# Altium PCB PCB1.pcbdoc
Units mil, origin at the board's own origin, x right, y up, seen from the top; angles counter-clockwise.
Board outline 1010 x 987.15 mil, 2 copper layers (Top Layer, Bottom Layer); 12 components, 8 nets, 48 pads, 12 vias.
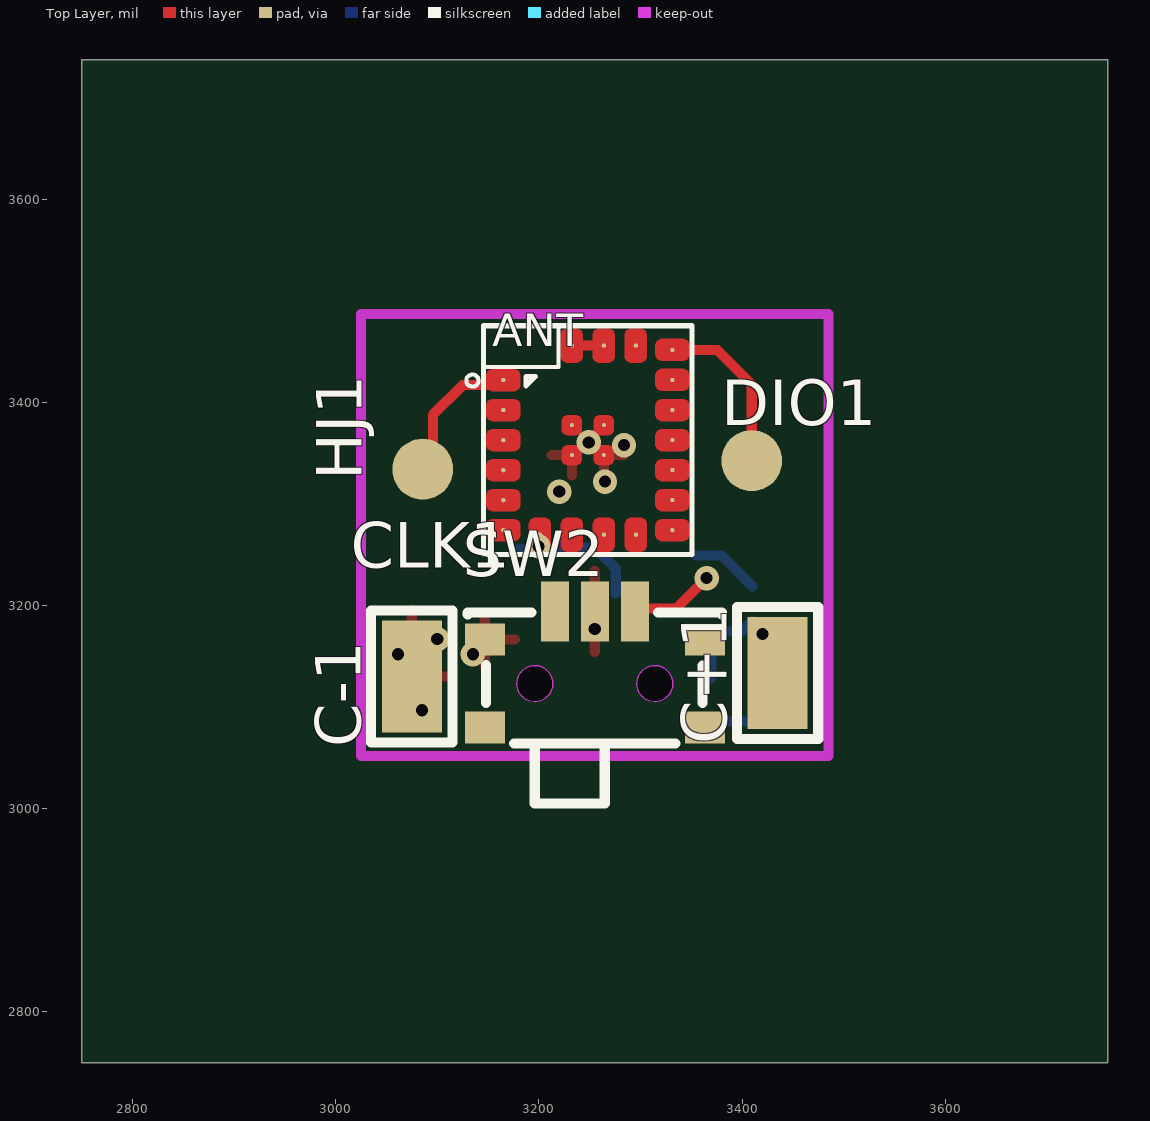
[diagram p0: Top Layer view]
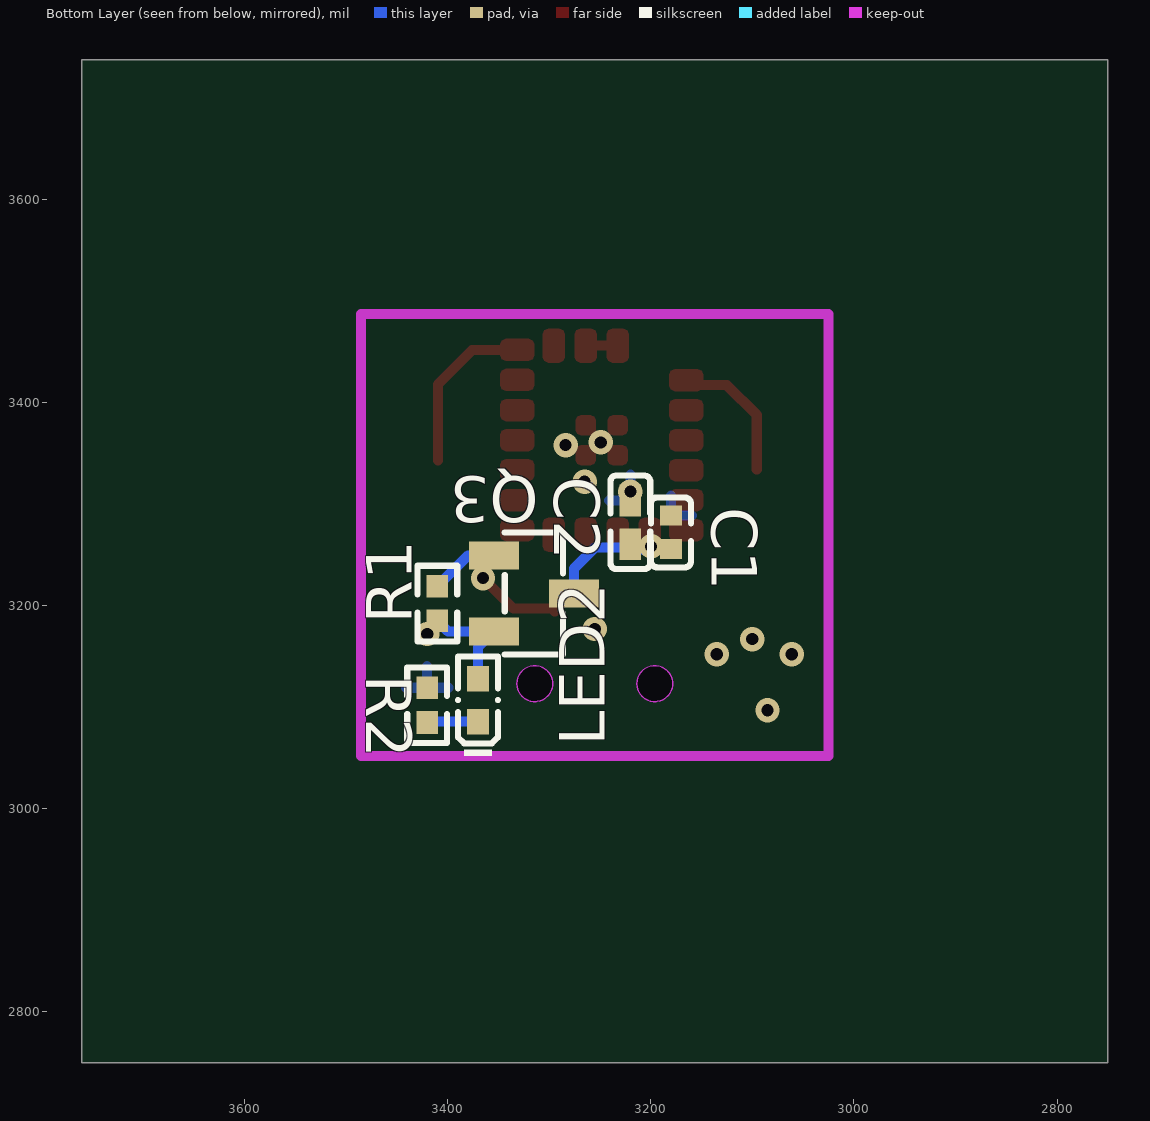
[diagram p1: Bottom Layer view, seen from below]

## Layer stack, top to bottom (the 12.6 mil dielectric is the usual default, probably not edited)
Top Layer: signal copper (thickness not stored)
Dielectric: dielectric 12.6, FR-4, Dk 4.8
Bottom Layer: signal copper (thickness not stored)

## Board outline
3760,2750 2750,2750 2750,3737.15 3760,3737.15

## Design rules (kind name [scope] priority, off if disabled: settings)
BoardOutlineClearance copperThickness1oz [All] p0: genericclearance=10 ignorepadtopadclearanceinfootprint=FALSE except(0: Arc-SplitContinuation Track-SplitContinuation SMDPad-SplitContinuation THPad-SplitContinuation Via-SplitContinuation Fill-SplitContinuation Poly-SplitContinuation Region-SplitContinuation Text-SplitContinuation; 6: Track-CutoutEdge SMDPad-CutoutEdge THPad-CutoutEdge Via-CutoutEdge Region-CutoutEdge; 11.8: Track-OutlineEdge SMDPad-OutlineEdge THPad-OutlineEdge Via-OutlineEdge Fill-OutlineEdge Region-OutlineEdge Poly-OutlineEdge Text-OutlineEdge Fill-CutoutEdge)
BoardOutlineClearance copperThickness2oz [All] p0: genericclearance=10 ignorepadtopadclearanceinfootprint=FALSE except(0: Arc-SplitContinuation Track-SplitContinuation SMDPad-SplitContinuation THPad-SplitContinuation Via-SplitContinuation Fill-SplitContinuation Poly-SplitContinuation Region-SplitContinuation Text-SplitContinuation; 6: Track-CutoutEdge SMDPad-CutoutEdge THPad-CutoutEdge Via-CutoutEdge Region-CutoutEdge; 11.8: Track-OutlineEdge SMDPad-OutlineEdge THPad-OutlineEdge Via-OutlineEdge Fill-OutlineEdge Region-OutlineEdge Poly-OutlineEdge Text-OutlineEdge Fill-CutoutEdge)
Clearance copperThickness1oz [(InNet('+3.3V') OR InNet('GND') OR InNet('$1N942') OR InNet('$1N941') OR InNet('$1N931') OR InNet('$1N605') OR InNet('$1N1928') OR InNet('$1N1997'))] p1: gap=7 ignorepadtopadclearanceinfootprint=FALSE except(4: Track-Track; 6: Track-SMDPad SMDPad-SMDPad Track-THPad SMDPad-THPad THPad-THPad Track-Via SMDPad-Via THPad-Via Via-Via SMDPad-Fill THPad-Fill Via-Fill Fill-Fill Track-Region SMDPad-Region THPad-Region Via-Region Region-Region Track-Poly SMDPad-Poly THPad-Poly Via-Poly Fill-Poly Region-Poly Poly-Poly Track-Text SMDPad-Text THPad-Text Via-Text Fill-Text Region-Text Poly-Text Text-Text; 6.9: Track-Hole SMDPad-Hole THPad-Hole Via-Hole Fill-Hole Region-Hole Poly-Hole Text-Hole Sheet-Hole; 11.8: Track-Fill Fill-Region Track-Sheet SMDPad-Sheet THPad-Sheet Via-Sheet Fill-Sheet Region-Sheet Poly-Sheet Text-Sheet)
Clearance copperThickness2oz [All] p1: gap=7 ignorepadtopadclearanceinfootprint=FALSE except(6: Track-SMDPad SMDPad-SMDPad Track-THPad SMDPad-THPad THPad-THPad Track-Via SMDPad-Via THPad-Via Via-Via SMDPad-Fill THPad-Fill Via-Fill Fill-Fill Track-Region SMDPad-Region THPad-Region Via-Region Region-Region Track-Poly SMDPad-Poly THPad-Poly Via-Poly Fill-Poly Region-Poly Poly-Poly Track-Text SMDPad-Text THPad-Text Via-Text Fill-Text Region-Text Poly-Text Text-Text; 6.9: Track-Hole SMDPad-Hole THPad-Hole Via-Hole Fill-Hole Region-Hole Poly-Hole Text-Hole Sheet-Hole; 8: Track-Track; 11.8: Track-Fill Fill-Region Track-Sheet SMDPad-Sheet THPad-Sheet Via-Sheet Fill-Sheet Region-Sheet Poly-Sheet Text-Sheet)
DiffPairsRouting differentialPair [All] p1: maxuncoupledlength=10 minlimit=6 maxlimit=6 mostfreqgap=6 toplayer_minwidth=5 toplayer_prefwidth=10 toplayer_maxwidth=100 bottomlayer_minwidth=5 bottomlayer_prefwidth=10 bottomlayer_maxwidth=100
PasteMaskExpansion pasteMaskExpansion [All] p1: expansion=0
PlaneConnect innerPlane [All] p1: planeconnectstyle=Relief reliefexpansion=20 reliefentries=4 reliefconductorwidth=10 reliefairgap=10
PolygonConnect copperRegion [All] p1: connectstyle=Relief reliefentries=4 reliefconductorwidth=10 polygonreliefangle="90 Angle" airgapwidth=10
RoutingVias viaSize [All] p1: viastyle="Through Hole" holewidth=12.0078 minholewidth=11.811 maxholewidth=248.0314 width=24.0158 minwidth=19.685 maxwidth=393.7008
SolderMaskExpansion solderMaskExpansion [All] p1: useseparateexpansions=TRUE expansion=2 expansionbottom=2
Width copperThickness1oz [All] p1: maxlimit=100 minlimit=5 preferedwidth=10
Width copperThickness2oz [All] p1: maxlimit=100 minlimit=8 preferedwidth=10

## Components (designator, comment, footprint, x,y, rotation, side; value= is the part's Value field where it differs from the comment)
C1 "CL05A105KA5NQNC" C0402#1 3180,3271.89 r270 bottom
C2 "10u" C0402#2 3220,3281.89 r270 bottom
C+1 "RH-5015" SMD_RH-5015 3435,3133.63 r90 top
C-1 "RH-5015" SMD_RH-5015 3074.86,3130.2 r90 top
CLK1 "TESTPOINT_D1.5mm" TESTPOINT_D1.5MM 3085.66,3334.12 r0 top
DIO1 "TESTPOINT_D1.5mm" TESTPOINT_D1.5MM 3409.49,3342.52 r0 top
HJ1 "HJ-180IMH" HJ-180IMH(LGA21) 3165,3421.89 r90 top
LED2 "XL-1005UGC_C2856703" LED0402-RD_GREEN 3370,3106.89 r90 bottom
Q3 "IRLML6401TRPBF" SOT-23-3_L2.9-W1.3-P1.90-LS2.4-BR 3315,3211.89 r0 bottom
R1 "10kΩ" R0402 3410,3201.89 r90 bottom
R2 "4.7K" R0402 3420,3101.89 r270 bottom
SW2 "MINI MSK12CO2" SW-SMD_MSK12CO2 3255,3136.89 r0 top

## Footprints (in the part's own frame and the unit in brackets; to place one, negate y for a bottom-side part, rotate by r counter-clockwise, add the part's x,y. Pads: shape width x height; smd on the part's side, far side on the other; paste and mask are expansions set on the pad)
C0402#1 [mm]
  rect 0.5x0.54 smd: 1(-0.42,0) 2(0.42,0)
  silkscreen extent -0.87,-0.5 0.87,0.5
C0402#2 [mm]
  rect 0.79x0.54 smd: 1(-0.545,0) 2(0.545,0)
  silkscreen extent -1.17,-0.5 1.17,0.5
HJ-180IMH(LGA21) [mm]
  round 0.11 smd: 1(0,0) 2(-0.75,0) 3(-1.501,0) 4(-2.251,0) 5(-3.002,0) 6(-3.752,0) 7(-3.865,-0.914) 8(-3.865,-1.714) 9(-3.865,-2.515) 10(-3.865,-3.315) 11(-3.751,-4.227) 12(-3.001,-4.227) 13(-2.25,-4.227) 14(-1.5,-4.227) 15(-0.75,-4.227) 16(0.001,-4.227) 17(0.751,-4.227) 18(0.862,-3.313) 19(0.862,-2.513) 20(0.862,-1.713)
  round 0.1 smd: 21(-1.876,-1.713) 21(-1.875,-2.513) 21(-1.126,-2.513) 21(-1.126,-1.713)
  Top Layer region: -0.137,0.425 0.137,0.425 0.235,0.385 0.275,0.288 0.275,-0.288 0.235,-0.385 0.137,-0.425 -0.137,-0.425 -0.235,-0.385 -0.275,-0.288 -0.275,0.288 -0.235,0.385
  Top Layer region: -0.888,0.425 -0.613,0.425 -0.516,0.385 -0.475,0.288 -0.475,-0.288 -0.516,-0.385 -0.613,-0.425 -0.888,-0.425 -0.985,-0.385 -1.025,-0.288 -1.025,0.288 -0.985,0.385
  Top Layer region: -1.638,0.425 -1.363,0.425 -1.266,0.385 -1.226,0.288 -1.226,-0.288 -1.266,-0.385 -1.363,-0.425 -1.638,-0.425 -1.736,-0.385 -1.776,-0.288 -1.776,0.288 -1.736,0.385
  Top Layer region: -2.389,0.425 -2.114,0.425 -2.016,0.385 -1.976,0.288 -1.976,-0.288 -2.016,-0.385 -2.114,-0.425 -2.389,-0.425 -2.486,-0.385 -2.526,-0.288 -2.526,0.288 -2.486,0.385
  Top Layer region: -3.139,0.425 -2.864,0.425 -2.767,0.385 -2.727,0.288 -2.727,-0.288 -2.767,-0.385 -2.864,-0.425 -3.139,-0.425 -3.236,-0.385 -3.277,-0.288 -3.277,0.288 -3.236,0.385
  Top Layer region: -3.89,0.425 -3.614,0.425 -3.517,0.385 -3.477,0.288 -3.477,-0.288 -3.517,-0.385 -3.614,-0.425 -3.89,-0.425 -3.987,-0.385 -4.027,-0.288 -4.027,0.288 -3.987,0.385
  Top Layer region: -4.29,-1.052 -4.29,-0.777 -4.25,-0.679 -4.152,-0.639 -4.152,-0.639 -3.577,-0.639 -3.577,-0.639 -3.48,-0.679 -3.44,-0.777 -3.44,-1.052 -3.48,-1.149 -3.577,-1.189 -4.152,-1.189 -4.25,-1.149
  Top Layer region: -4.29,-1.852 -4.29,-1.577 -4.25,-1.48 -4.152,-1.439 -3.577,-1.439 -3.48,-1.48 -3.44,-1.577 -3.44,-1.852 -3.48,-1.949 -3.577,-1.989 -4.152,-1.989 -4.25,-1.949
  Top Layer region: -4.29,-2.652 -4.29,-2.377 -4.25,-2.28 -4.152,-2.24 -3.577,-2.24 -3.48,-2.28 -3.44,-2.377 -3.44,-2.652 -3.48,-2.749 -3.577,-2.79 -4.152,-2.79 -4.25,-2.749
  Top Layer region: -4.29,-3.452 -4.29,-3.177 -4.25,-3.08 -4.152,-3.04 -3.577,-3.04 -3.48,-3.08 -3.44,-3.177 -3.44,-3.452 -3.48,-3.55 -3.577,-3.59 -4.152,-3.59 -4.25,-3.55
  Top Layer region: -3.614,-4.652 -3.888,-4.652 -3.986,-4.612 -4.026,-4.514 -4.026,-3.939 -3.986,-3.842 -3.888,-3.802 -3.614,-3.802 -3.516,-3.842 -3.476,-3.939 -3.476,-4.514 -3.516,-4.612
  Top Layer region: -2.863,-4.652 -3.138,-4.652 -3.235,-4.612 -3.276,-4.514 -3.276,-3.939 -3.235,-3.842 -3.138,-3.802 -2.863,-3.802 -2.766,-3.842 -2.726,-3.939 -2.726,-4.514 -2.766,-4.612
  Top Layer region: -2.113,-4.652 -2.388,-4.652 -2.485,-4.612 -2.525,-4.514 -2.525,-3.939 -2.485,-3.842 -2.388,-3.802 -2.113,-3.802 -2.016,-3.842 -1.975,-3.939 -1.975,-4.514 -2.016,-4.612
  Top Layer region: -1.363,-4.652 -1.638,-4.652 -1.735,-4.612 -1.775,-4.514 -1.775,-3.939 -1.735,-3.842 -1.638,-3.802 -1.363,-3.802 -1.265,-3.842 -1.225,-3.939 -1.225,-3.939 -1.225,-4.514 -1.225,-4.514 -1.265,-4.612
  Top Layer region: -0.612,-4.652 -0.887,-4.652 -0.984,-4.612 -1.025,-4.514 -1.025,-3.939 -0.984,-3.842 -0.887,-3.802 -0.612,-3.802 -0.515,-3.842 -0.475,-3.939 -0.475,-4.514 -0.515,-4.612
  Top Layer region: 0.138,-4.652 -0.137,-4.652 -0.234,-4.612 -0.274,-4.514 -0.274,-3.939 -0.234,-3.842 -0.137,-3.802 0.138,-3.802 0.235,-3.842 0.276,-3.939 0.276,-4.514 0.235,-4.612
  Top Layer region: 0.888,-4.652 0.613,-4.652 0.516,-4.612 0.476,-4.514 0.476,-3.939 0.516,-3.842 0.613,-3.802 0.888,-3.802 0.986,-3.842 1.026,-3.939 1.026,-4.514 0.986,-4.612
  Top Layer region: 1.287,-3.176 1.287,-3.45 1.247,-3.548 1.15,-3.588 0.574,-3.588 0.477,-3.548 0.437,-3.45 0.437,-3.176 0.477,-3.078 0.574,-3.038 1.15,-3.038 1.247,-3.078
  Top Layer region: 1.287,-2.376 1.287,-2.65 1.247,-2.748 1.15,-2.788 0.574,-2.788 0.477,-2.748 0.437,-2.65 0.437,-2.376 0.477,-2.278 0.574,-2.238 1.15,-2.238 1.247,-2.278
  Top Layer region: 1.287,-1.576 1.287,-1.85 1.247,-1.948 1.15,-1.988 0.574,-1.988 0.477,-1.948 0.437,-1.85 0.437,-1.576 0.477,-1.478 0.574,-1.438 1.15,-1.438 1.247,-1.478
  Top Layer region: -1.626,-1.588 -1.626,-1.838 -1.663,-1.926 -1.751,-1.963 -2.001,-1.963 -2.089,-1.926 -2.126,-1.838 -2.126,-1.588 -2.089,-1.5 -2.001,-1.463 -1.751,-1.463 -1.663,-1.5
  Top Layer region: -0.876,-1.588 -0.876,-1.838 -0.913,-1.926 -1.001,-1.963 -1.251,-1.963 -1.339,-1.926 -1.376,-1.838 -1.376,-1.588 -1.339,-1.5 -1.251,-1.463 -1.001,-1.463 -0.913,-1.5
  Top Layer region: -1.625,-2.388 -1.625,-2.638 -1.662,-2.726 -1.75,-2.763 -2,-2.763 -2.088,-2.726 -2.125,-2.638 -2.125,-2.388 -2.088,-2.3 -2,-2.263 -1.75,-2.263 -1.662,-2.3
  Top Layer region: -0.876,-2.388 -0.876,-2.638 -0.913,-2.726 -1.001,-2.763 -1.251,-2.763 -1.339,-2.726 -1.376,-2.638 -1.376,-2.388 -1.339,-2.3 -1.251,-2.263 -1.001,-2.263 -0.913,-2.3
  silkscreen extent -4.36,-4.72 1.37,0.92
LED0402-RD_GREEN [mm]
  rect 0.636x0.54 smd: 1(-0.538,0) 2(0.538,0)
  silkscreen extent -1.39,-0.54 1.09,0.54
R0402 [mm]
  rect 0.566x0.54 smd: 1(-0.433,0) 2(0.433,0)
  silkscreen extent -0.94,-0.5 0.94,0.5
SMD_RH-5015 [mm]
  rect 2.8x1.5 smd: 1(0,0)
  silkscreen extent -1.65,-1.02 1.65,1.02
SOT-23-3_L2.9-W1.3-P1.90-LS2.4-BR [mm]
  rect 1.25x0.7 smd: 1(1,-0.95) 2(1,0.95) 3(-1,0)
  silkscreen extent -0.73,-1.53 0.73,1.53
SW-SMD_MSK12CO2 [mm]
  rect 0.7x1.5 smd: 1(-1,1.45) 2(0,1.45) 3(1,1.45)
  rect 1x0.8 smd: 4(-2.75,0.75) 5(2.75,0.75) 6(-2.75,-1.45) 7(2.75,-1.45)
  Board Outline Layer circle w0.005: c-1.5,-0.35 r0.45
  Board Outline Layer circle w0.005: c1.5,-0.35 r0.45
  Board Outline Layer region: -1.05,-0.35 -1.094,-0.545 -1.219,-0.702 -1.4,-0.789 -1.6,-0.789 -1.78,-0.702 -1.905,-0.545 -1.95,-0.35 -1.95,-0.35 -1.905,-0.155 -1.78,0.002 -1.6,0.089 -1.4,0.089 -1.219,0.002 -1.094,-0.155 -1.05,-0.35
  Board Outline Layer region: 1.95,-0.35 1.906,-0.545 1.781,-0.702 1.6,-0.789 1.4,-0.789 1.22,-0.702 1.095,-0.545 1.05,-0.35 1.05,-0.35 1.095,-0.155 1.22,0.002 1.4,0.089 1.6,0.089 1.781,0.002 1.906,-0.155 1.95,-0.35
  Multi-Layer board cut-out: -1.05,-0.35 -1.094,-0.545 -1.219,-0.702 -1.4,-0.789 -1.6,-0.789 -1.78,-0.702 -1.905,-0.545 -1.95,-0.35 -1.95,-0.35 -1.905,-0.155 -1.78,0.002 -1.6,0.089 -1.4,0.089 -1.219,0.002 -1.094,-0.155 -1.05,-0.35
  Multi-Layer board cut-out: 1.95,-0.35 1.906,-0.545 1.781,-0.702 1.6,-0.789 1.4,-0.789 1.22,-0.702 1.095,-0.545 1.05,-0.35 1.05,-0.35 1.095,-0.155 1.22,0.002 1.4,0.089 1.6,0.089 1.781,0.002 1.906,-0.155 1.95,-0.35
  silkscreen extent -3.17,-3.35 3.17,1.43
TESTPOINT_D1.5MM [mil]
  round 60 smd: 1(0,0)

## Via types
v1: diameter 24.02, hole 12.01, Top Layer to Bottom Layer, 12 vias

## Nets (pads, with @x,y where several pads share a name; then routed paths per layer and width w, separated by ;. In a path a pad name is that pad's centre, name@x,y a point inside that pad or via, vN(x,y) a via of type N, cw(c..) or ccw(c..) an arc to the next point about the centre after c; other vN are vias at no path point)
$1N605: Q3.1 R1.2 SW2.3 | length 152.5
  Top Layer w10: SW2.3 3297.28,3196.89 3335,3196.89 v1(3365,3226.89)
  Bottom Layer w10: Q3.1 3379.64,3249.29 R1.2
$1N931: HJ1.19 HJ1.20 | length 31.5
  Top Layer w10: 3227.44,3455.83 3258.94,3455.83
$1N941: DIO1.1 HJ1.17 | length 172.1
  Top Layer w10: 3326.42,3451.46 3375.55,3451.46 3409.49,3417.52 DIO1.1
$1N942: CLK1.1 HJ1.1 | length 137
  Top Layer w10: CLK1.1@3095.66,3334.12 3095.66,3387.55 3125,3416.89 3160,3416.89 HJ1.1
$1N1928: C+1.1 LED2.2 Q3.2 R1.1 | length 112.8
  Bottom Layer w10: LED2.2 3370,3158.86 Q3.2 3399.64,3174.49 R1.1
  other v1: 3420,3171.89
$1N1997: LED2.1 R2.2 | length 50.4
  Bottom Layer w10: LED2.1 3419.15,3085.7 R2.2
+3.3V: C1.2 C2.2 HJ1.7 Q3.3 | length 132.1
  Bottom Layer w10: C1.2 3214.92,3255.35 C2.2 3223.54,3256.89 3255,3256.89 3275.63,3236.26 Q3.3
  other v1: 3199.59,3258.17
GND: C1.1 C2.1 C-1.1 HJ1.21 R2.1 SW2.2 SW2.4
  other v1: 3085,3096.89 3061.23,3151.89 3135,3151.89 3100,3166.89 3255,3176.8 3220,3312.09 3265,3321.89 3283.78,3357.87 3249.09,3360.47
pads on no net: HJ1.2 HJ1.3 HJ1.4 HJ1.5 HJ1.6 HJ1.8 HJ1.9 HJ1.10 HJ1.11 HJ1.12 HJ1.13 HJ1.14 HJ1.15 HJ1.16 HJ1.18 SW2.1 SW2.5 SW2.6 SW2.7

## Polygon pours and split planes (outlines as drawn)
GND on Bottom Layer (solid, remove dead copper, pour order 2): 3000,3381.89 3510,3381.89 3510,3046.89 3000,3046.89
GND on Top Layer (solid, remove dead copper, pour order 0): 3010,3381.89 3485,3381.89 3485,3046.89 3010,3046.89

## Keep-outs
Board Outline Layer:
  lines w10: 3025,3051.89 3485,3051.89 3485,3486.89 3025,3486.89 3025,3051.89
